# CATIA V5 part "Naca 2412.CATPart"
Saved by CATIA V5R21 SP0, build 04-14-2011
Part number: Naca 2412
Bounding box of the stored display mesh (mm): x 0 to 200, y -8.46 to 15.76, z -41.25 to 41.25
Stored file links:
  C:\Users\andre\OneDrive\Documentos\UNB-FGA\3_Semestre\Sistemas Aeroespaciais\Naca 2412.CATPart
  C:\Users\andre\AppData\Local\Temp\Rar$DIa18808.12376\NACA 2412 3D Aerofoil.CATPart
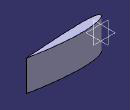
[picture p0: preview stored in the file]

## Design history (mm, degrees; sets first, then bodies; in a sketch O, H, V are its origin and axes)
Body1 (main body)
  Sketch1 on xy-plane, origin (0, 0, 0), H (1, 0, 0), V (0, 1, 0)
    unspec C1
    unspec C2
  Pad1: profile Sketch1, direction (0, 0, 1), length 41.25, mirrored extent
